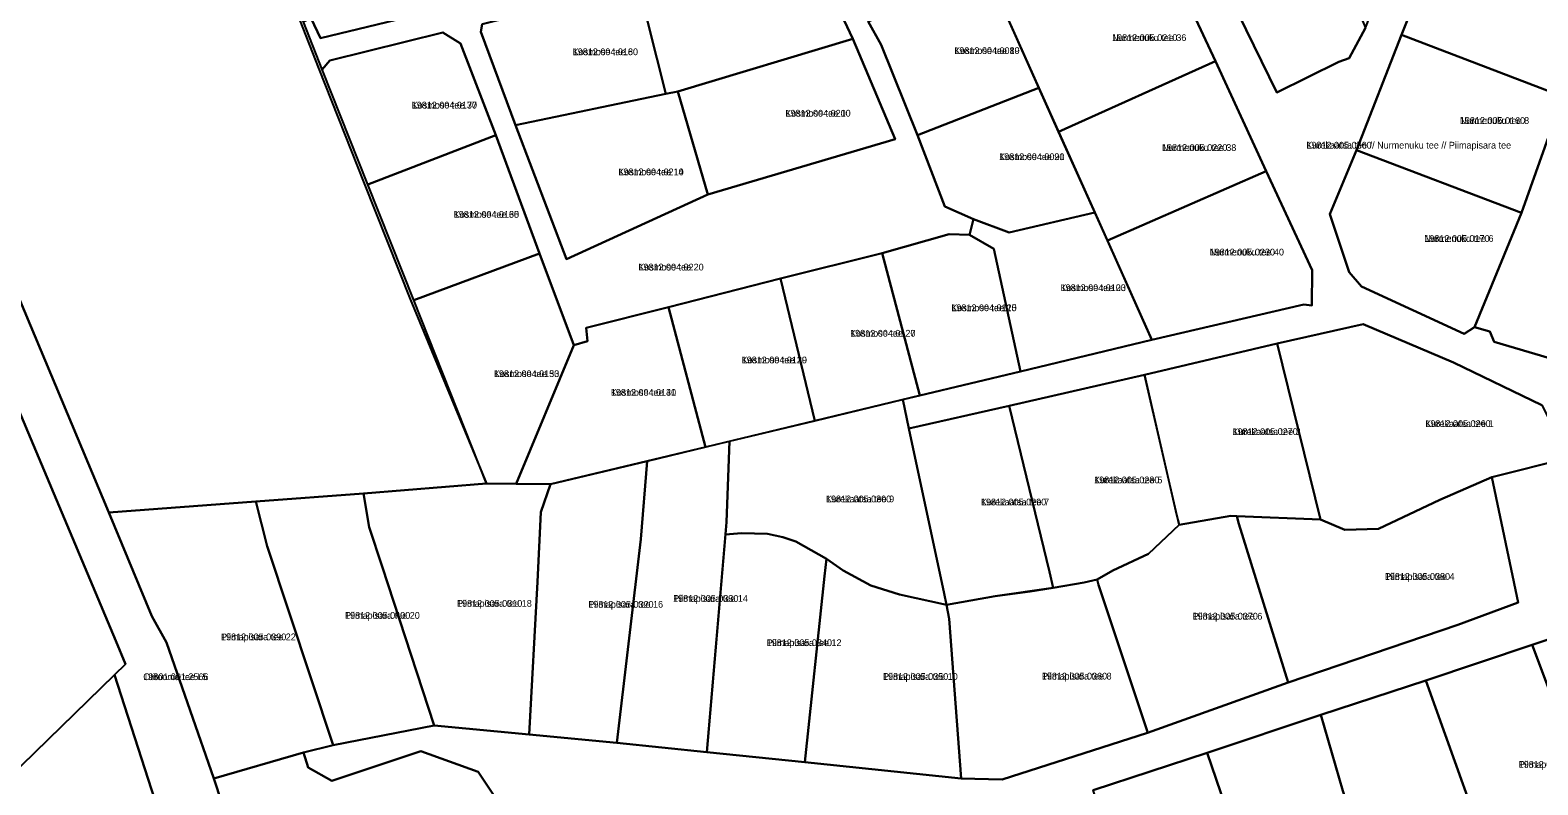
# Model space of a CAD drawing. Extents: x 516875 to 535633, y 6574491 to 6593094.
# Drawn here: x 517287.6 to 517622.6, y 6585327.5 to 6585495.2 of the extents above; entities that cross this region are included whole.
import ezdxf

# ---------------------------------------------------------------- set-up
doc = ezdxf.new("R2010")
doc.units = 0
for name, color, linetype in [('L_AADRESS', 7, 'Continuous'), ('PIIR', 7, 'Continuous'), ('TUNNUS', 7, 'Continuous')]:
    doc.layers.add(name, color=color, linetype=linetype)

msp = doc.modelspace()

# ---------------------------------------------------------------- linework, layer by layer
at = {"layer": 'PIIR'}
for points in [[(517353.23, 6585640.14), (517343.94, 6585640.44), (517326.53, 6585636.6), (517294.91, 6585629.81), (517306.14, 6585601.62), (517313.96, 6585581.91), (517325.11, 6585554.1), (517327.26, 6585548.48), (517337.06, 6585523.73), (517347.54, 6585497.29), (517351.73, 6585486.7), (517361.88, 6585461.11), (517372.08, 6585435.37), (517389.06, 6585394.42), (517361.73, 6585392.23), (517337.78, 6585390.43), (517305.11, 6585387.97), (517271.21, 6585468.82), (517216.44, 6585599.27), (517351.7, 6585659.34)], [(517563.74, 6585564.32), (517536.18, 6585539.54), (517547.54, 6585516.3), (517564.67, 6585481.34), (517578.43, 6585488.11), (517580.74, 6585488.97), (517584.33, 6585495.68), (517600.64, 6585537.05), (517607.47, 6585554.38), (517621.56, 6585589.6), (517620.23, 6585596.34), (517618.4, 6585599.51), (517616.02, 6585602.28), (517613.35, 6585604.31), (517609.72, 6585605), (517582.83, 6585581.51)], [(517375.15, 6585498.93), (517352.14, 6585493.4), (517350.08, 6585497.78), (517348.34, 6585497.03), (517337.85, 6585523.46), (517367.29, 6585530.78)], [(517547.54, 6585516.3), (517565.08, 6585531.46), (517573.92, 6585520), (517584.33, 6585495.68), (517580.74, 6585488.97), (517578.43, 6585488.11), (517564.67, 6585481.34)], [(517602.61, 6585519.89), (517636.05, 6585506.82), (517633.44, 6585499.85), (517630.09, 6585483.27), (517628.2, 6585480.41), (517592.35, 6585494.1)], [(517388.06, 6585496.5), (517387.76, 6585494.77), (517395.45, 6585474.04), (517406.82, 6585444.29), (517438.21, 6585458.67), (517479.83, 6585470.94), (517470.42, 6585493.22), (517462.16, 6585510.88), (517455.72, 6585513.27), (517422.79, 6585505.16)], [(517428.85, 6585481.01), (517422.79, 6585505.16), (517455.72, 6585513.27), (517462.16, 6585510.88), (517470.42, 6585493.22), (517431.54, 6585481.56)], [(517511.79, 6585482.36), (517505.05, 6585497.44), (517539.5, 6585512.87), (517551.03, 6585488.24), (517516.16, 6585472.6)], [(517476.7, 6585491.92), (517473.83, 6585497.06), (517500.36, 6585507.91), (517511.79, 6585482.36), (517484.79, 6585471.8)], [(517428.85, 6585481.01), (517395.45, 6585474.04), (517387.76, 6585494.77), (517388.06, 6585496.5), (517422.79, 6585505.16)], [(517352.54, 6585486.45), (517354.22, 6585488.38), (517379.29, 6585494.63), (517383.27, 6585492.21), (517391.12, 6585471.81), (517362.69, 6585460.87)], [(517592.35, 6585494.1), (517628.2, 6585480.41), (517619.02, 6585454.56), (517582.32, 6585468.5)], [(517431.54, 6585481.56), (517470.42, 6585493.22), (517479.83, 6585470.94), (517438.21, 6585458.67)], [(517516.16, 6585472.6), (517551.03, 6585488.24), (517562.27, 6585463.84), (517526.99, 6585448.41)], [(517626.71, 6585423.8), (517625.2, 6585422.28), (517612.91, 6585425.92), (517612.01, 6585428.24), (517608.6, 6585429.17), (517619.02, 6585454.56), (517628.2, 6585480.41), (517630.09, 6585483.27), (517648.79, 6585444.78), (517653.56, 6585433.7), (517630.18, 6585422.69)], [(517395.45, 6585474.04), (517428.85, 6585481.01), (517431.54, 6585481.56), (517438.21, 6585458.67), (517406.82, 6585444.29)], [(517490.86, 6585456.01), (517484.79, 6585471.8), (517511.79, 6585482.36), (517524.19, 6585454.65), (517505.14, 6585450.23), (517497.22, 6585453.18)], [(517362.69, 6585460.87), (517391.12, 6585471.81), (517400.8, 6585445.56), (517372.9, 6585435.14)], [(517261.59, 6585466.48), (517306.67, 6585359.47), (517308.83, 6585354.33), (517306.35, 6585351.92), (517282.72, 6585328.92), (517281.21, 6585332.08), (517221.5, 6585456.72), (517257.65, 6585465.52)], [(517363.93, 6585219.13), (517355.29, 6585214.67), (517351.33, 6585212.62), (517306.35, 6585351.92), (517308.83, 6585354.33), (517306.67, 6585359.47), (517261.59, 6585466.48), (517271.21, 6585468.82), (517305.11, 6585387.97), (517314.63, 6585364.95), (517317.95, 6585359.12), (517328.47, 6585328.95), (517337.16, 6585302.33), (517345.14, 6585278.12), (517346.9, 6585272.74)], [(517580.7, 6585441.36), (517576.45, 6585454.26), (517582.32, 6585468.5), (517619.02, 6585454.56), (517608.6, 6585429.17), (517606.27, 6585427.73), (517583.45, 6585438.22)], [(517526.99, 6585448.41), (517562.27, 6585463.84), (517572.5, 6585441.85), (517572.43, 6585434.02), (517570.62, 6585434.19), (517536.84, 6585426.36)], [(517038.61, 6585356.85), (517061.8, 6585364.36), (517066.51, 6585412.44), (517103.89, 6585423.94), (517151.32, 6585438.55), (517221.5, 6585456.72), (517281.21, 6585332.08), (517282.72, 6585328.92), (517306.35, 6585351.92), (517351.33, 6585212.62), (517304.11, 6585187.79), (517235.26, 6585195.4), (517074.05, 6585291.89), (517021.05, 6585351.17)], [(517501.79, 6585446.58), (517496.33, 6585449.7), (517497.22, 6585453.18), (517505.14, 6585450.23), (517524.19, 6585454.65), (517536.84, 6585426.36), (517507.68, 6585419.36)], [(517476.97, 6585445.65), (517491.8, 6585449.8), (517496.33, 6585449.7), (517501.79, 6585446.58), (517507.68, 6585419.36), (517485.32, 6585413.99)], [(517372.9, 6585435.14), (517400.8, 6585445.56), (517408.47, 6585425.18), (517395.63, 6585394.35), (517389.06, 6585394.42)], [(517454.36, 6585440.02), (517476.97, 6585445.65), (517485.32, 6585413.99), (517461.99, 6585408.39)], [(517429.46, 6585433.62), (517454.36, 6585440.02), (517461.99, 6585408.39), (517437.69, 6585402.55)], [(517395.63, 6585394.35), (517408.47, 6585425.18), (517411.5, 6585426.1), (517411.15, 6585429), (517429.46, 6585433.62), (517437.69, 6585402.55), (517403.23, 6585394.27)], [(517583.82, 6585429.85), (517603.87, 6585421.34), (517623.54, 6585411.83), (517629.54, 6585400.18), (517612.39, 6585395.86), (517600.88, 6585390.84), (517587.23, 6585384.38), (517579.78, 6585384.14), (517574.37, 6585386.43), (517564.69, 6585425.52)], [(517535.21, 6585418.57), (517564.69, 6585425.52), (517574.37, 6585386.43), (517555.77, 6585387.21), (517554.46, 6585387.26), (517542.92, 6585385.27)], [(517536.1, 6585378.84), (517528.17, 6585375.1), (517524.72, 6585373.09), (517521.82, 6585372.47), (517514.95, 6585371.29), (517514.16, 6585374.82), (517505.17, 6585411.73), (517535.21, 6585418.57), (517542.37, 6585387.49), (517542.92, 6585385.27)], [(517442.37, 6585385.82), (517442.99, 6585403.82), (517461.99, 6585408.39), (517481.56, 6585413.08), (517482.85, 6585406.69), (517490.72, 6585369.99), (517491.26, 6585367.46), (517480.81, 6585369.77), (517474.4, 6585371.78), (517468.3, 6585375.14), (517464.59, 6585377.73), (517457.74, 6585381.56), (517454.89, 6585382.53), (517451.44, 6585383.26), (517445.68, 6585383.38), (517442.14, 6585383.13)], [(517482.85, 6585406.69), (517505.17, 6585411.73), (517514.16, 6585374.82), (517514.95, 6585371.29), (517502.05, 6585369.42), (517491.26, 6585367.46), (517490.72, 6585369.99)], [(517423.35, 6585382.06), (517424.76, 6585399.44), (517442.99, 6585403.82), (517442.37, 6585385.82), (517438.01, 6585334.73), (517418, 6585336.8)], [(517400.33, 6585372.63), (517401.13, 6585388.09), (517403.23, 6585394.27), (517424.76, 6585399.44), (517423.35, 6585382.06), (517418, 6585336.8), (517398.54, 6585338.66)], [(517365.85, 6585376.01), (517362.98, 6585384.78), (517361.73, 6585392.23), (517389.06, 6585394.42), (517395.63, 6585394.35), (517403.23, 6585394.27), (517401.13, 6585388.09), (517400.33, 6585372.63), (517398.54, 6585338.66), (517377.4, 6585340.71)], [(517556.19, 6585385.52), (517555.77, 6585387.21), (517574.37, 6585386.43), (517579.78, 6585384.14), (517587.23, 6585384.38), (517600.88, 6585390.84), (517612.39, 6585395.86), (517618.3, 6585368.01), (517604.84, 6585363.06), (517567.13, 6585350.23)], [(517340.29, 6585380.49), (517354.96, 6585336.35), (517348.36, 6585334.67), (517328.47, 6585328.95), (517317.95, 6585359.12), (517314.63, 6585364.95), (517305.11, 6585387.97), (517337.78, 6585390.43)], [(517340.29, 6585380.49), (517337.78, 6585390.43), (517361.73, 6585392.23), (517362.98, 6585384.78), (517365.85, 6585376.01), (517377.4, 6585340.71), (517354.96, 6585336.35)], [(517535.81, 6585339.47), (517525.04, 6585371.91), (517524.72, 6585373.09), (517528.17, 6585375.1), (517536.1, 6585378.84), (517542.92, 6585385.27), (517554.46, 6585387.26), (517555.77, 6585387.21), (517556.19, 6585385.52), (517567.13, 6585350.23), (517535.92, 6585339.09)], [(517442.14, 6585383.13), (517445.68, 6585383.38), (517451.44, 6585383.26), (517454.89, 6585382.53), (517457.74, 6585381.56), (517464.59, 6585377.73), (517464.17, 6585373.89), (517459.79, 6585332.55), (517438.01, 6585334.73)], [(517464.17, 6585373.89), (517464.59, 6585377.73), (517468.3, 6585375.14), (517474.4, 6585371.78), (517480.81, 6585369.77), (517491.26, 6585367.46), (517491.86, 6585364.36), (517494.47, 6585328.89), (517459.79, 6585332.55)], [(517494.47, 6585328.89), (517491.86, 6585364.36), (517491.26, 6585367.46), (517502.05, 6585369.42), (517509.82, 6585370.45), (517514.95, 6585371.29), (517521.82, 6585372.47), (517524.72, 6585373.09), (517525.04, 6585371.91), (517535.81, 6585339.47), (517535.92, 6585339.09), (517503.59, 6585328.72)], [(517621.4, 6585358.58), (517645.73, 6585366.76), (517663.34, 6585319.94), (517639.03, 6585311.71)], [(517597.74, 6585350.7), (517621.4, 6585358.58), (517639.03, 6585311.71), (517614.54, 6585303.75)], [(517582.66, 6585316.09), (517579.3, 6585326.14), (517574.43, 6585343.02), (517597.74, 6585350.7), (517614.54, 6585303.75), (517589.29, 6585295.29)], [(517549.17, 6585334.61), (517574.43, 6585343.02), (517579.3, 6585326.14), (517582.66, 6585316.09), (517589.29, 6585295.29), (517565.22, 6585287.56)], [(517328.47, 6585328.95), (517348.36, 6585334.67), (517349.4, 6585331.37), (517354.69, 6585328.38), (517374.47, 6585334.99), (517387.15, 6585330.4), (517394.88, 6585318.83), (517380.48, 6585315.81), (517337.16, 6585302.33)], [(517532.39, 6585301.12), (517529.67, 6585309.52), (517523.81, 6585326.29), (517549.17, 6585334.61), (517565.22, 6585287.56), (517539.53, 6585279.24)]]:
    msp.add_lwpolyline(points, close=True, dxfattribs=at)
for points in [[(517622.74, 6585570.44), (517612.61, 6585545.06), (517602.61, 6585519.89), (517592.35, 6585494.1), (517582.32, 6585468.5), (517576.45, 6585454.26), (517580.7, 6585441.36), (517583.45, 6585438.22), (517606.27, 6585427.73), (517608.6, 6585429.17), (517612.01, 6585428.24), (517612.91, 6585425.92), (517625.2, 6585422.28)], [(517623.54, 6585411.83), (517603.87, 6585421.34), (517583.82, 6585429.85), (517564.69, 6585425.52), (517535.21, 6585418.57), (517505.17, 6585411.73), (517482.85, 6585406.69), (517481.56, 6585413.08), (517485.32, 6585413.99), (517507.68, 6585419.36), (517536.84, 6585426.36), (517570.62, 6585434.19), (517572.43, 6585434.02), (517572.5, 6585441.85), (517562.27, 6585463.84), (517551.03, 6585488.24), (517539.5, 6585512.87)], [(517473.83, 6585497.06), (517476.7, 6585491.92), (517484.79, 6585471.8), (517490.86, 6585456.01), (517497.22, 6585453.18), (517496.33, 6585449.7), (517491.8, 6585449.8), (517476.97, 6585445.65), (517454.36, 6585440.02), (517429.46, 6585433.62), (517411.15, 6585429), (517411.5, 6585426.1), (517408.47, 6585425.18), (517400.8, 6585445.56), (517391.12, 6585471.81), (517383.27, 6585492.21), (517379.29, 6585494.63), (517354.22, 6585488.38), (517352.54, 6585486.45), (517348.34, 6585497.03)], [(517350.08, 6585497.78), (517352.14, 6585493.4), (517375.15, 6585498.93)], [(517394.88, 6585318.83), (517387.15, 6585330.4), (517374.47, 6585334.99), (517354.69, 6585328.38), (517349.4, 6585331.37), (517348.36, 6585334.67), (517354.96, 6585336.35), (517377.4, 6585340.71), (517398.54, 6585338.66), (517418, 6585336.8), (517438.01, 6585334.73), (517459.79, 6585332.55), (517494.47, 6585328.89), (517503.59, 6585328.72), (517535.92, 6585339.09), (517567.13, 6585350.23), (517604.84, 6585363.06), (517618.3, 6585368.01), (517612.39, 6585395.86), (517629.54, 6585400.18)], [(517645.73, 6585366.76), (517621.4, 6585358.58), (517597.74, 6585350.7), (517574.43, 6585343.02), (517549.17, 6585334.61), (517523.81, 6585326.29)]]:
    msp.add_lwpolyline(points, dxfattribs=at)

# ---------------------------------------------------------------- texts
at = {"layer": 'L_AADRESS'}
for s, p in [('Nurmenuku tee 36', (517528.04, 6585492.74)), ('Kosmose tee 6', (517408.19, 6585489.6)), ('Kosmose tee 19', (517492.98, 6585489.86)), ('Kosmose tee 37', (517372.41, 6585477.75)), ('Kosmose tee 10', (517455.45, 6585475.95)), ('Nurmenuku tee 8', (517605.32, 6585474.33)), ('Nurmenuku tee 38', (517539.14, 6585468.32)), ('Kurekaatsa tee // Nurmenuku tee // Piimapisara tee', (517571.21, 6585468.85)), ('Kosmose tee 21', (517502.94, 6585466.29)), ('Kosmose tee 14', (517418.33, 6585462.92)), ('Kosmose tee 35', (517381.75, 6585453.48)), ('Nurmenuku tee 40', (517549.73, 6585445.1)), ('Nurmenuku tee 6', (517597.42, 6585448.12)), ('Kosmose tee', (517422.78, 6585441.77)), ('Kosmose tee 23', (517516.59, 6585437.19)), ('Kosmose tee 25', (517492.32, 6585432.73)), ('Kosmose tee 27', (517469.84, 6585427.07)), ('Kosmose tee 33', (517390.68, 6585418.09)), ('Kosmose tee 29', (517445.73, 6585421.14)), ('Kosmose tee 31', (517416.66, 6585413.94)), ('Kurekaatsa tee 3', (517554.79, 6585405.22)), ('Kurekaatsa tee 1', (517597.65, 6585407)), ('Kurekaatsa tee 5', (517524.05, 6585394.49)), ('Kurekaatsa tee 9', (517464.45, 6585390.27)), ('Kurekaatsa tee 7', (517498.9, 6585389.58)), ('Piimapisara tee 4', (517588.64, 6585373.04)), ('Piimapisara tee 14', (517430.5, 6585368.16)), ('Piimapisara tee 20', (517357.59, 6585364.39)), ('Piimapisara tee 18', (517382.48, 6585367.06)), ('Piimapisara tee 16', (517411.65, 6585366.85)), ('Piimapisara tee 6', (517545.93, 6585364.22)), ('Piimapisara tee 22', (517330.04, 6585359.62)), ('Piimapisara tee 12', (517451.3, 6585358.33)), ('Otitooma tee L5', (517312.76, 6585350.77)), ('Piimapisara tee 10', (517477.13, 6585350.82)), ('Piimapisara tee 8', (517512.43, 6585350.9)), ('Piimapisara tee 3', (517618.39, 6585331.29))]:
    msp.add_text(s, height=1.5, dxfattribs=at).set_placement(p)
at = {"layer": 'TUNNUS'}
for s, p in [('19812:005:0210', (517528.04, 6585492.74)), ('19812:004:0180', (517408.19, 6585489.6)), ('19812:004:0080', (517492.98, 6585489.86)), ('19812:004:0170', (517372.41, 6585477.75)), ('19812:004:0200', (517455.45, 6585475.95)), ('19812:005:0160', (517605.32, 6585474.33)), ('19812:005:0220', (517539.14, 6585468.32)), ('19812:005:0560', (517571.21, 6585468.85)), ('19812:004:0090', (517502.94, 6585466.29)), ('19812:004:0210', (517418.33, 6585462.92)), ('19812:004:0160', (517381.75, 6585453.48)), ('19812:005:0230', (517549.73, 6585445.1)), ('19812:005:0170', (517597.42, 6585448.12)), ('19812:004:0220', (517422.78, 6585441.77)), ('19812:004:0100', (517516.59, 6585437.19)), ('19812:004:0110', (517492.32, 6585432.73)), ('19812:004:0120', (517469.84, 6585427.07)), ('19812:004:0150', (517390.68, 6585418.09)), ('19812:004:0130', (517445.73, 6585421.14)), ('19812:004:0140', (517416.66, 6585413.94)), ('19812:005:0270', (517554.79, 6585405.22)), ('19812:005:0260', (517597.65, 6585407)), ('19812:005:0280', (517524.05, 6585394.49)), ('19812:005:0300', (517464.45, 6585390.27)), ('19812:005:0290', (517498.9, 6585389.58)), ('19812:005:0380', (517588.64, 6585373.04)), ('19812:005:0330', (517430.5, 6585368.16)), ('19812:005:0310', (517382.48, 6585367.06)), ('19812:005:0320', (517411.65, 6585366.85)), ('19812:005:0400', (517357.59, 6585364.39)), ('19812:005:0370', (517545.93, 6585364.22)), ('19812:005:0390', (517330.04, 6585359.62)), ('19812:005:0340', (517451.3, 6585358.33)), ('19801:001:2566', (517312.76, 6585350.77)), ('19812:005:0350', (517477.13, 6585350.82)), ('19812:005:0360', (517512.43, 6585350.9)), ('19812:005:0530', (517618.39, 6585331.29))]:
    msp.add_text(s, height=1.5, dxfattribs=at).set_placement(p)

doc.saveas('drawing.dxf')
